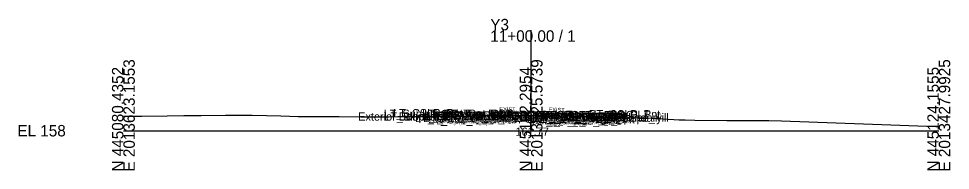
# Model space of a CAD drawing. Extents: x -26 to 203, y -10 to 5017.
# Drawn here: x -25.7 to 202.8, y 1990.3 to 2027.4 of the extents above; entities that cross this region are included whole.
import ezdxf

# ---------------------------------------------------------------- set-up
doc = ezdxf.new("R2010")
doc.units = 0
for name, color, linetype in [('Default', 7, 'Continuous'), ('Exist Cross Section Cell', 7, 'Continuous'), ('Exist XS Center Line Elevation Label', 7, 'Continuous'), ('Exist XS Ground Line', 7, 'Continuous'), ('Prop XS SE Text', 7, 'Continuous'), ('Scratch_Level_0', 7, 'Continuous')]:
    doc.layers.add(name, color=color, linetype=linetype)

msp = doc.modelspace()

# ---------------------------------------------------------------- linework, layer by layer
at = {"layer": 'Exist Cross Section Cell'}
for p, q in [((100, 2000), (100, 2024.57)), ((0, 2000), (100, 2000)), ((100, 2000), (200, 2000))]:
    msp.add_line(p, q, dxfattribs=at)
at = {"layer": 'Exist XS Ground Line'}
msp.add_lwpolyline([(0, 2003.55), (2.33, 2003.58), (4.56, 2003.59), (10.7, 2003.64), (14.81, 2003.74), (19.07, 2003.7), (25.06, 2003.82), (29.4, 2003.83), (31.57, 2003.77), (38.65, 2003.66), (42.87, 2003.47), (46.48, 2003.46), (52.95, 2003.45), (58.23, 2003.4), (61.81, 2003.4), (64.17, 2003.4), (67.35, 2003.44), (71.2, 2003.44), (74.92, 2003.46), (75.41, 2003.47), (75.98, 2003.48), (80.87, 2003.49), (85.11, 2003.58), (86.93, 2003.68), (87.74, 2003.78), (88.08, 2003.75), (89.04, 2003.72), (97.4, 2003.76), (100.22, 2003.77), (102.95, 2003.7), (112.33, 2003.46), (113.28, 2003.58), (113.62, 2003.6), (114.23, 2003.3), (126.45, 2003.19), (127.55, 2003.18), (129.59, 2003.07), (136.3, 2002.7), (137.8, 2002.66), (140.17, 2002.61), (148.05, 2002.53), (153.38, 2002.5), (158.3, 2002.47), (161.42, 2002.44), (188.26, 2001.45), (199.3, 2001.03), (200, 2001)], dxfattribs=at)

# ---------------------------------------------------------------- texts
at = {"layer": 'Default'}
msp.add_text('-', height=0.0001, dxfattribs=at).set_placement((0, 2000))
at = {"layer": 'Exist Cross Section Cell'}
for s, p in [('Y3', (90, 2024.57)), ('11+00.00 / 1', (90, 2021.77)), ('EL 158', (-26, 1998.6))]:
    msp.add_text(s, height=2.8, dxfattribs=at).set_placement(p)
for s, p in [('E 2013623.1553', (2.8, 1990)), ('E 2013525.5739', (102.8, 1990)), ('E 2013427.9925', (202.8, 1990)), ('N 445080.4352', (0, 1990)), ('N 445102.2954', (100, 1990)), ('N 445124.1555', (200, 1990))]:
    msp.add_text(s, height=2.8, rotation=90, dxfattribs=at).set_placement(p)
at = {"layer": 'Exist XS Center Line Elevation Label'}
msp.add_text('161.77', height=2, dxfattribs=at).set_placement((96.18, 1998.77))
at = {"layer": 'Prop XS SE Text'}
for rotation, p in [(0.2865, (92.22, 2004.73)), (358.5679, (104.25, 2004.66))]:
    msp.add_text('EXIST.', height=1, rotation=rotation, dxfattribs=at).set_placement(p)
at = {"layer": 'Scratch_Level_0'}
for s, p in [('Exterior Boundary', (57.59, 2002.46)), ('LT_Sub_Trench_Out_DLT', (63.84, 2003.16)), ('LT_Slope_Fill', (63.97, 2002.46)), ('LT_CSLP_Pnt', (66.17, 2003.31)), ('LT_CG_Top_Face', (73.26, 2003.12)), ('LT_CG_Top_BOC', (73.78, 2003.12)), ('LT_PV_Sub_Tie_Out', (73.96, 2002.72)), ('LT_CG_Top_Gut', (74.24, 2002.62)), ('LT_PV_OEEOP_EG', (76.54, 2002.72)), ('LT_PV2_OEOT', (78.17, 2002.46)), ('LT_PV2_OEEOP', (78.31, 2002.46)), ('LT_PV1_OEOT', (78.74, 2002.71)), ('LT_PV1_OEEOP', (78.87, 2002.59)), ('RT_PV_IEEOP_EG', (88.14, 2002.77)), ('LT_PV_IEEOP_EG', (88.19, 2002.77)), ('RT_PV2_IEEOP', (89.91, 2002.52)), ('LT_PV2_IEEOP', (89.95, 2002.52)), ('RT_PV1_IEEOP', (90.47, 2002.64)), ('LT_PV1_IEEOP', (90.52, 2002.64)), ('PV2_PGL', (93.91, 2002.52)), ('PV1_PGL', (94.47, 2002.77)), ('RT_PV_Sub_Tie_Out', (95.88, 2002.49)), ('RT_Sub_Trench_Out_DLT', (97.28, 2002.88)), ('RT_PV_OEEOP_EG', (98.5, 2002.49)), ('RT_PV2_OEEOP', (100.26, 2002.24)), ('RT_PV1_OEEOP', (100.83, 2002.37)), ('RT_CG_Top_Face', (101.21, 2002.84)), ('RT_PV2_OEOT', (102.13, 2002.22)), ('RT_CG_Top_Gut', (102.19, 2002.34)), ('RT_PV1_OEOT', (102.69, 2002.47)), ('RT_CG_Top_BOC', (102.74, 2002.84)), ('Exterior Boundary', (110.65, 2002.19)), ('RT_CSLP_Pnt', (114.13, 2003.03)), ('RT_Slope_Fill', (116.98, 2002.19)), ('LT_CG1_Shelf_Out', (71.55, 2002.11)), ('LT_CG_Bot_BOC', (73.81, 2002.11)), ('LT_Sub_OEOP', (74.78, 2001.77)), ('LT_CG_Bot_IE', (77.91, 2002.12)), ('LT_Sub_OEOT', (78.08, 2001.79)), ('LT_PV3_OEOT', (78.17, 2002.12)), ('LT_Sub_OEEOP', (78.21, 2001.79)), ('LT_PV3_OEEOP', (78.31, 2002.13)), ('RT_PV3_IEEOP', (89.91, 2002.18)), ('LT_PV3_IEEOP', (89.95, 2002.18)), ('RT_Sub_OEEOP', (100.17, 2001.57)), ('RT_PV3_OEEOP', (100.26, 2001.91)), ('RT_CG1_Shelf_Out', (101.5, 2001.81)), ('RT_CG_Bot_IE', (101.87, 2001.88)), ('RT_Sub_OEOT', (102.03, 2001.55)), ('RT_PV3_OEOT', (102.13, 2001.88)), ('RT_CG_Bot_BOC', (102.77, 2001.82)), ('RT_Sub_OEOP', (105.4, 2001.47))]:
    msp.add_text(s, height=2, dxfattribs=at).set_placement(p)

doc.saveas('drawing.dxf')
